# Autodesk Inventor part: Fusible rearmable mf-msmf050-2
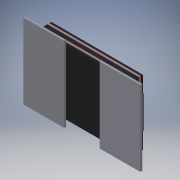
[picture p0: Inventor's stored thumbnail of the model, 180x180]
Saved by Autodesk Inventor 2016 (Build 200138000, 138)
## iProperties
Created: 2018-03
Part Number: Fusible rearmable mf-msmf050-2
Material: Générique
Document SubType Name: Modeling
Designer: Bruno
Density: 1 g/cm^3
Appearance: Par défaut
Author: Bruno
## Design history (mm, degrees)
feature "Composite1"
body "Srf1"
